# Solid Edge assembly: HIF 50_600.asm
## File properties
Title: Zylinder
Author: ahadarics
Template: iso assembly.asm
Last saved by: ahadarics
Revision: 55
Application: Solid Edge
Username: ahadarics
Dokumentum tartalom típus: 1
Document Number: HIF 50/600
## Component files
Kit_2.par
Kit_1.par
Profilrohr 50_600.par
Kolbenstange 50_600.par
Mutter.par
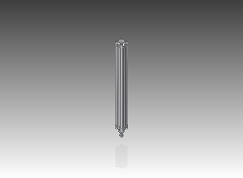
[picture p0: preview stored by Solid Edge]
